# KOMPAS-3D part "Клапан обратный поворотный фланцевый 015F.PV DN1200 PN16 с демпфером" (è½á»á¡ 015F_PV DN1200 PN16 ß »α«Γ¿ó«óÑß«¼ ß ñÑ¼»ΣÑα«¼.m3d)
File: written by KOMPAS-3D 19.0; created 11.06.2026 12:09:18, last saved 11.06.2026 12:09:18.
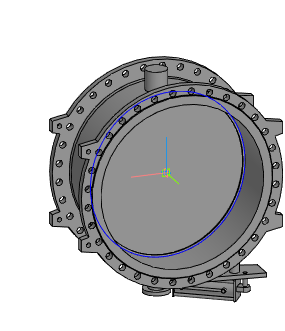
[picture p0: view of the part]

Document properties: Автор: Энергия; Полное имя файла: Z:\3.Личные\kachalov\001_3d для проектировщиков\5.5 Тип 015F.PV Клапан обратный поворотный с двумя эксцентриками\_stp_Клапан 015F.PV DN300-DN1200 с противовесом с демпфером\Клапан 015F_PV DN1200 PN16 с противовесом с демпфером.m3d

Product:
- Part/product: Клапан обратный поворотный фланцевый 015F.PV DN1200 PN16 с демпфером

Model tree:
1. Операция без истории:1
2. Сплайн:1
     Координата Y = 30; Координата Z = 600; Вес = 1; Координата X = 1200; Координата Y = 187.983; Координата Z = 600; Вес = 0.333333; Координата X = 1200; Координата Y = 187.983; Координата Z = -600; Вес = 0.333333; Координата Y = 30; Координата Z = -600; Вес = 1; Координата X = -1200; Координата Y = -127.983; Координата Z = -600; Вес = 0.333333; Координата X = -1200; Координата Y = -127.983; Координата Z = 600; Вес = 0.333333; Порядок = 4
